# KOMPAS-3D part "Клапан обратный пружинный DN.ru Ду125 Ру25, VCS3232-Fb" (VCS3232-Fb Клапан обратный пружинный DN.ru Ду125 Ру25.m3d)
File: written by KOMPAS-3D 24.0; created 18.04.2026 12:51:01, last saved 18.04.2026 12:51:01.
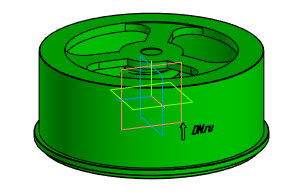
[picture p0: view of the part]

Document properties: Автор: 712; Полное имя файла: C:\Users\712\Desktop\Новая папка (4)\VCS3232-Fb Клапан обратный пружинный DN.ru Ду125 Ру25.m3d

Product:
- Component: Пружина 1086-1017 ГОСТ 18793-80  | qty 1  | additional columns: 3953604318-4147491677-0; Деталь; Пользователь Windows; c; Шероховатость не задана; Да; Сталь 10  ГОСТ 1050-88; source file: Деталь_1.m3d
- Body: Тело 1  | qty 1
    Масса: 4.808113
- Part/product: Клапан обратный пружинный DN.ru Ду125 Ру25  | designation VCS3232-Fb
    Масса: 3.9
    Раздел спецификации: Прочие изделия
    Примечание: D100-04022
    additional columns: 071bd168-1a06-425c-849c-e99e84a96128; Деталь; 712; c; Шероховатость не задана; Да

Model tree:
1. Операция без истории:2

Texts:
  VCS3232-Fb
